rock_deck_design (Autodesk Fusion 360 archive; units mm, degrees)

design "rock_deck_design" references "PCB - Modulo", "rock_pcb", "rock_deck_lid_v2"
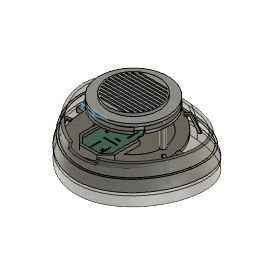
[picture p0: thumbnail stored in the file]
part number: 2025-12-11-21-33-59-411
part number: 2025-12-11-21-35-01-840
part number: 2025-12-11-22-10-40-260
part number: 2025-12-11-23-59-30-911
part number: 2025-12-12-00-11-13-812
part number: 2025-12-12-00-51-12-144
part number: 2025-12-12-02-11-26-460
part number: 2025-12-12-03-30-52-712
part number: 2025-12-12-20-44-37-742
part number: 2025-12-13-21-39-32-884
part number: 2025-12-13-21-39-32-904
part number: 2025-12-13-21-39-32-911
part number: 2025-12-14-05-35-21-238
parameter "led_outer" = 96
parameter "pcb_height" = 30
parameter "acrylic_height" = 3
parameter "d8" = 2.5
sketch "Sketch1" plane through (0, 0, 0) normal (0, 0, 1) x axis (1, 0, 0)
sketch "Sketch2" plane through (0, 0, 0) normal (0, 0, 1) x axis (1, 0, 0)
  circle C1 centre (0, 0) radius 48
  point P1 (0, 0)
  point P2 (0, 0)
  coincident P1 P2
  dimension "d3" diameter C1 = 96 (= "led_outer")
sketch "Sketch3" plane through (0, 0, 0) normal (0, 0, 1) x axis (1, 0, 0)
sketch "Sketch1" plane through (0, 0, 0) normal (0, 0, 1) x axis (1, 0, 0)
  line L1 (35.3875, -35.3231) -> (25.5948, -24.5999)
  line L2 (42.7648, -25.907) -> (31.0257, -17.2527)
  circle C1 centre (0, 0) radius 35.5
  arc A1 centre (0, 0) radius 50 clockwise from (35.3875, -35.3231) to (42.7648, -25.907)
  circle C2 centre (-12.1143, -8.7606) radius 1.25
  circle C3 centre (-16.5143, 28.7434) radius 1.25
  circle C4 centre (17.4857, 28.7434) radius 1.25
  circle C5 centre (11.8857, -8.7606) radius 1.25
  circle C6 centre (-12.1143, -8.7606) radius 1.25
  circle C7 centre (-16.5143, 28.7434) radius 1.25
  circle C8 centre (17.4857, 28.7434) radius 1.25
  circle C9 centre (11.8857, -8.7606) radius 1.25
  point P1 (0, 0)
  point P2 (0, 0)
  point P3 (0, 0)
  point P4 (25.5948, -24.5999)
  point P6 (31.0257, -17.2527)
  coincident P1 P2
  coincident P1 P3
  coincident C1 P4
  coincident C1 P6
  dimension "d9" diameter A1 = 100 (= "led_outer + 4 mm")
  dimension "d15" diameter C1 = 71 (= "led_outer - 25 mm")
  dimension "d216" diameter C5 = 2.5
  dimension "d217" diameter C2 = 2.5
  dimension "d218" diameter C4 = 2.5
  dimension "d219" diameter C3 = 2.5
  dimension "d220" diameter C9 = 2.5
  dimension "d221" diameter C6 = 2.5
  dimension "d222" diameter C8 = 2.5
  dimension "d223" diameter C7 = 2.5
extrude "Extrude1" new body sketch "Sketch1" profile of A1 against normal blind 2 bodies "lid_bottom"
sketch "Sketch2" plane through (0, 0, 0) normal (0, 0, 1) x axis (1, 0, 0)
extrude "Extrude2" add sketch "Sketch2" along normal blind 4.42
sketch "Sketch3" plane through (0, 0, 0) normal (0, 1, 0) x axis (1, 0, 0)
extrude "Extrude3" new body sketch "Sketch1" profile of C1 along normal blind 6
extrude "Extrude4" add sketch "Sketch1" profile of C1 against normal blind 4
extrude "Extrude5" add of existing geometry blind 2
extrude "Extrude6" add of existing geometry blind 1
sketch "Sketch4" plane through (0, 0, 7) normal (0, 0, 1) x axis (-1, 0, 0)
  circle C1 centre (0, 0) radius 35.5
  circle C2 centre (0, 0) radius 50
  point P1 (0, 0)
  point P3 (0, 0)
  coincident P1 P3
  dimension "d25" diameter C2 = 100 (= "led_outer + 4 mm")
extrude "Extrude7" new body sketch "Sketch4" along normal blind 3 (= "acrylic_height") bodies "Acrylic"
move "Move1"
component_insert "Component Insert2"
sketch "Sketch6" plane through (0, 0, 7) normal (0, 0, 1) x axis (-1, 0, 0)
  line L1 (-19, 44.4881) -> (20, 44.4881)
  line L2 (-19, -15.0119) -> (-19, 44.4881)
  line L3 (20, -15.0119) -> (-19, -15.0119)
  line L4 (20, 44.4881) -> (20, -15.0119)
  line L5 (9.5, 67.5) -> (-8.5, 67.5)
  line L6 (9.5, 49.5) -> (9.5, 67.5)
  line L7 (-8.5, 49.5) -> (9.5, 49.5)
  line L8 (-8.5, 67.5) -> (-8.5, 49.5)
  circle C1 centre (0, 0) radius 35.5
  circle C2 centre (11.8857, -8.7606) radius 1.25
  circle C3 centre (11.8857, -8.7606) radius 1.25
  circle C4 centre (-12.1143, -8.7606) radius 1.25
  circle C5 centre (17.4857, 28.7434) radius 1.25
  circle C6 centre (-16.5143, 28.7434) radius 1.25
  point P11 (11.8857, -8.7606)
  point P12 (11.8857, -8.7606)
  point P3 (20, 44.4881)
  point P4 (-19, 44.4881)
  point P6 (20, -15.0119)
  point P7 (-8.5, 67.5)
  point P8 (9.5, 67.5)
  point P10 (-8.5, 49.5)
  horizontal L1
  vertical L2
  horizontal L3
  vertical L4
  horizontal L5
  vertical L6
  horizontal L7
  vertical L8
  coincident P11 P12
  dimension "d32" distance P3 P4 = 39
  dimension "d33" distance P3 P6 = 59.5
  dimension "d34" distance P7 P8 = 18
  dimension "d35" distance P7 P10 = 18
  dimension "d46" diameter C2 = 2.5
  dimension "d48" diameter C3 = 2.5
  dimension "d213" diameter C4 = 2.5
  dimension "d214" diameter C5 = 2.5
  dimension "d215" diameter C6 = 2.5
extrude "Extrude8" new body sketch "Sketch6" profile of L1 L2 L3 L4 L5 L6 L7 L8 along normal blind 22
extrude "Extrude9" add of existing geometry blind 3
move "Move2"
move_face "MoveFace1"
move "Move3"
move "Move4"
move "Move5"
sketch "Sketch7" plane through (0, 0, -34.9) normal (0, 0, -1) x axis (1, 0, 0)
  line L1 (-140, -20.8619) -> (-140, 38.6381)
  line L2 (-101, -20.8619) -> (-140, -20.8619)
  line L3 (-101, 38.6381) -> (-101, -20.8619)
  line L4 (-140, 38.6381) -> (-101, 38.6381)
  line L5 (10.1267, 38.6381) -> (-9.8733, 38.6381)
  line L6 (10.1267, 36.0381) -> (10.1267, 38.6381)
  line L7 (-9.8733, 36.0381) -> (10.1267, 36.0381)
  line L8 (-9.8733, 38.6381) -> (-9.8733, 36.0381)
  point P6 (-9.8733, 38.6381)
  point P7 (10.1267, 38.6381)
  point P9 (-9.8733, 36.0381)
  horizontal L5
  vertical L6
  horizontal L7
  vertical L8
  coincident L4 P6
  dimension "d40" distance P6 P7 = 20
  dimension "d41" distance P6 P9 = 2.6
extrude "Extrude10" cut sketch "Sketch7" profile of L1 L2 L3 L4 L6 L7 L8 against normal blind 23
sketch "Sketch9" plane through (0, 0, -34.9) normal (0, 0, -1) x axis (1, 0, 0)
extrude "Extrude12" cut of existing geometry blind -60
component_from_bodies "Body->Comp2"
remove_instance "RemoveInstance1"
move_face "MoveFace2"
extrude "Extrude13" add of existing geometry blind 3
extrude "Extrude14" new body sketch "Sketch2" along normal blind 10
extrude "Extrude15" cut sketch "Sketch2" against normal blind 20
extrude "Extrude16" cut of existing geometry blind -5
extrude "Extrude17" cut of existing geometry blind -3.3
component_from_bodies "Body->Comp3"
copy_paste_bodies "CutPasteBodies1"
move "Move1"
extrude "Extrude1" cut of existing geometry blind -10 bodies "lid_bottom (1)"
extrude "Extrude5" cut of existing geometry blind -2
sketch "Sketch1" plane through (0, 0, -2) normal (0, 0, -1) x axis (1, 0, 0)
  line L1 (-29.3095, 19.0404) -> (-25.3095, 19.0404)
  line L2 (-29.3095, 49.4381) -> (-29.3095, 19.0404)
  line L3 (-25.3095, 19.0404) -> (-25.3095, 49.4381)
  line L4 (10, 59.5028) -> (-15.3954, 59.5028)
  line L5 (-15.3954, 63.5028) -> (10, 63.5028)
  line L6 (22.8952, 13.6845) -> (22.8952, 50.4973)
  line L7 (18.8952, 13.6845) -> (22.8952, 13.6845)
  line L8 (18.8952, 50.4973) -> (18.8952, 13.6845)
  line L9 (-15.3954, 63.5028) -> (-29.3095, 49.4381)
  line L10 (22.8952, 50.4973) -> (10, 63.5028)
  line L11 (18.8952, 50.4973) -> (10, 59.5028)
  line L12 (-25.3095, 49.4381) -> (-15.3954, 59.5028)
  line L13 (10.605, 22.1471) -> (2.605, 22.1471)
  line L14 (10.605, 18.1471) -> (10.605, 22.1471)
  line L15 (2.605, 18.1471) -> (10.605, 18.1471)
  line L16 (2.605, 22.1471) -> (2.605, 18.1471)
  curve K1 (-58.3992, -18.229) -> (-58.3992, -18.229)
  curve K2 (-32.0553, -67.1742) -> (3.8106, -67.1918)
  circle C1 centre (-14.2027, 1.6355) radius 0.75
  circle C2 centre (-14.2027, 1.6355) radius 2.5
  circle C3 centre (0, 0) radius 43
  point P24 (-14.1223, -67.183)
  point P3 (-25.3095, 19.0404)
  point P4 (-29.3095, 19.0404)
  point P7 (-15.3954, 59.5028)
  point P10 (-15.3954, 63.5028)
  point P11 (18.8952, 50.4973)
  point P12 (22.8952, 50.4973)
  point P16 (2.605, 22.1471)
  point P17 (10.605, 22.1471)
  point P19 (2.605, 18.1471)
  horizontal L1
  vertical L2
  vertical L3
  horizontal L4
  horizontal L5
  vertical L6
  horizontal L7
  vertical L8
  concentric C1 C2
  horizontal L13
  vertical L14
  horizontal L15
  vertical L16
  midpoint P24 K2
  dimension "d103" diameter C1 = 1.5
  dimension "d104" distance P3 P4 = 4
  dimension "d105" distance P7 P10 = 4
  dimension "d106" distance P11 P12 = 4
  dimension "d125" diameter C2 = 5
  dimension "d134" distance P16 P17 = 8
  dimension "d135" distance P16 P19 = 4
extrude "Extrude2" new body sketch "Sketch1" profile of L2 L3 L4 L5 L6 L8 L9 L10 L11 L12 against normal blind 6
extrude "Extrude3" add sketch "Sketch1" profile of L2 L3 L4 L5 L6 L8 L9 L10 L11 L12 along normal blind 2
extrude "Extrude4" add of existing geometry blind 2
move "Move1"
move "Move2"
extrude "Extrude5" new body sketch "Sketch1" profile of C1 along normal blind 6
extrude "Extrude6" add sketch "Sketch1" profile of C1 L1 L2 L3 L4 L6 L7 L8 L11 L12 along normal blind 4
extrude "Extrude7" cut of existing geometry blind -6
extrude "Extrude8" new body sketch "Sketch1" profile of C1 against normal blind 6
extrude "Extrude9" add of existing geometry blind 2
move_face "MoveFace1"
move "Move3"
extrude "Extrude10" add sketch "Sketch1" profile of C1 C2 against normal blind 4
extrude "Extrude11" cut of existing geometry blind -2
move "Move4"
extrude "Extrude12" new body sketch "Sketch1" profile of L1 L2 L3 L6 L7 L8 along normal blind 4
extrude "Extrude13" add sketch "Sketch1" profile of L1 L2 L3 L6 L7 L8 against normal blind 2
move "Move5"
position "Position1"
extrude "Extrude1" cut sketch "Sketch1" profile of L13 L14 L15 L16 along normal blind 50
move "Move6"
position "Position2"
extrude "Extrude15" add of existing geometry blind 4
extrude "Extrude16" add of existing geometry blind 2
cylinder_primitive "CylinderPrimitive1" Height 14 Diameter 15
move "Move7"
move "Move8"
move_face "MoveFace2"
move "Move9"
extrude "Extrude17" add of existing geometry blind 44
extrude "Extrude18" cut of existing geometry blind -5
extrude "Extrude19" cut of existing geometry blind -5
extrude "Extrude20" add of existing geometry blind 3
delete_face "DeleteFace1"
sketch "Sketch1" plane through (0, 0, 1.7) normal (0, 0, 1) x axis (-1, 0, 0)
  circle C1 centre (0, 0) radius 43
  circle C2 centre (-0.1571, 0.0176) radius 3.5
  circle C3 centre (0, -30) radius 2.5
  circle C4 centre (30, 0) radius 2.5
  circle C5 centre (0, 30) radius 2.5
  circle C6 centre (-30, 0) radius 2.5
  circle C7 centre (18.732, -19.3591) radius 2.5
  circle C8 centre (-19.9991, -19.3591) radius 2.5
  circle C9 centre (-20, 20) radius 2.5
  circle C10 centre (20, 20) radius 2.5
  dimension "d158" diameter C2 = 7
  dimension "d159" diameter C3 = 5
  dimension "d160" diameter C4 = 5
  dimension "d161" diameter C5 = 5
  dimension "d162" diameter C6 = 5
  dimension "d163" diameter C7 = 5
  dimension "d164" diameter C8 = 5
  dimension "d165" diameter C9 = 5
  dimension "d166" diameter C10 = 5
move_face "MoveFace3"
extrude "Extrude21" cut of existing geometry blind -10.4
move "Move8"
sketch "Sketch3" plane through (0, 0, 2.8) normal (0, 0, -1) x axis (1, 0, 0)
  circle C1 centre (0, 0) radius 40
  circle C2 centre (0, 0) radius 43
  dimension "d204" diameter C1 = 80
sketch "Sketch4" plane through (0, 0, -5.1) normal (0, 0, -1) x axis (1, 0, 0)
  circle C1 centre (0, 0) radius 43
sketch "Sketch1" plane through (0, 0, 1.7) normal (0, 0, 1) x axis (-1, 0, 0)
  circle C1 centre (0, 0) radius 35.5
  circle C2 centre (0, 0) radius 38
  point P1 (0, 0)
  point P3 (0, 0)
  coincident P1 P3
  dimension "d206" diameter C2 = 76 (= "led_outer - 20 mm")
extrude "Extrude1" new body sketch "Sketch1" against normal blind 11.6
sketch "Sketch2" plane through (0, 0, 1.7) normal (0, 0, 1) x axis (-1, 0, 0)
  circle C1 centre (0, 0) radius 43
  circle C2 centre (0, 0) radius 35.5
  point P1 (0, 0)
  point P3 (0, 0)
  coincident P1 P3
  dimension "d209" diameter C2 = 71 (= "led_outer - 25 mm")
extrude "Extrude2" add sketch "Sketch2" profile of C2 against normal blind 4
move "Move2"
extrude "Extrude1" new body sketch "Sketch6" profile of C2 C3 C4 C5 C6 along normal blind 5
move "Move1"
position "Position3"
extrude "Extrude18" cut of existing geometry blind -3
move "Move2"
component_insert "Component Insert2"
move "Move3"
move_face "MoveFace1"
move "Move4"
move "Move5"
move "Move6"
extrude "Extrude2" add of existing geometry blind 6
cylinder_primitive "CylinderPrimitive1" Height 5 Diameter 5
extrude "Extrude3" add of existing geometry blind 4
extrude "Extrude4" add of existing geometry blind 7
copy_paste_bodies "CopyPasteBodies1"
move "Move7"
copy_paste_bodies "CopyPasteBodies3"
move "Move9"
copy_paste_bodies "CopyPasteBodies4"
move "Move10"
delete_face "DeleteFace1"
delete_face "DeleteFace2"
position "Position5"
extrude "Extrude5" cut of existing geometry blind -10
extrude "Extrude3" add of existing geometry blind 7 bodies "lid_bottom (1)"
extrude "Extrude4" add of existing geometry blind 3.8
sketch "Sketch2" plane through (0, 0, -7.2307) normal (0, 0, -1) x axis (1, 0, 0)
  line L1 (35.4029, 35.2772) -> (30.6766, 30.1019)
  line L2 (37.1188, 21.6875) -> (42.7802, 25.8612)
  arc A1 centre (0.0154, -0.0459) radius 50 clockwise from (42.7802, 25.8612) to (35.4029, 35.2772)
  arc A2 centre (0.0154, -0.0459) radius 43 clockwise from (30.6766, 30.1019) to (37.1188, 21.6875)
  circle C1 centre (0, 0) radius 35.5
  point P1 (0, 0)
  point P7 (0, 0)
  coincident P1 P7
  dimension "d249" diameter C1 = 71 (= "led_outer - 20 mm - 5 mm")
extrude "Extrude6" cut sketch "Sketch2" profile of C1 against normal blind 10
extrude "Extrude7" add of existing geometry blind 10
extrude "Extrude8" cut of existing geometry blind -1
offset_faces "OffsetFaces1" distance -0.25
component_from_bodies "Body->Comp1"
component_insert "Component Insert3"
extrude "Extrude28" new body sketch "Sketch1" profile of C1 L1 L2 L3 L4 L5 L6 L7 L8 L9 L10 L11 L12 C2 L13 L14 L15 L16 C3 K1 along normal blind 4
move "Move11"
move_face "MoveFace5"
move "Move12"
position "Position6"
extrude "Extrude9" add of existing geometry blind 42
copy_paste_bodies "CutPasteBodies1"
extrude "Extrude29" cut of existing geometry blind -4
extrude "Extrude30" new body of existing geometry blind -15
move "Move13"
extrude "Extrude31" cut of existing geometry blind -11
copy_paste_bodies "CopyPasteBodies2"
move "Move6"
copy_paste_bodies "CopyPasteBodies3"
move "Move7"
move "Move8"
offset_faces "OffsetFaces1" distance 4
scale "Scale1" ScaleFactor 1.2
move "Move9"
extrude "Extrude8" cut of existing geometry blind -9
copy_paste_bodies "CopyPasteBodies4"
move "Move10"
sketch "Sketch6" plane through (0, 0, 0) normal (0, 1, 0) x axis (1, 0, 0)
  line L1 (-75.3685, 36.7721) -> (-58.2562, 36.7721)
  line L2 (-75.3685, 42.7721) -> (-75.3685, 36.7721)
  line L3 (-58.2562, 42.7721) -> (-75.3685, 42.7721)
  line L4 (-58.2562, 36.7721) -> (-58.2562, 42.7721)
  line L5 (-38.9696, 36.7721) -> (-58.2562, 42.7721)
  line L6 (-58.2562, 36.7721) -> (-38.9696, 36.7721)
  point P2 (-58.2562, 36.7721)
  point P5 (-58.2562, 42.7721)
  horizontal L1
  vertical L2
  horizontal L3
  vertical L4
  perpendicular L4 L6
  dimension "d285" distance P2 P5 = 6
extrude "Extrude34" new body sketch "Sketch6" along normal blind 8 and against normal blind 8
hole "Hole1" HoleDepth 6 HoleDiameter 9 TipAngle 180
copy_paste_bodies "CopyPasteBodies3"
move "Move17"
scale "Scale2" ScaleFactor 1.1
move "Move11"
move "Move12"
offset_faces "OffsetFaces2" distance 10
extrude "Extrude9" cut of existing geometry blind -11
copy_paste_bodies "CopyPasteBodies5"
copy_paste_bodies "CopyPasteBodies6"
copy_paste_bodies "CopyPasteBodies7"
move "Move13"
component_from_bodies "Body->Comp2"
component_from_bodies "Body->Comp3"
component_from_bodies "Body->Comp4"
offset_faces "OffsetFaces3" distance 1
fillet "Fillet1" radius 0.25
sketch "Sketch4" plane through (0, 0, 0) normal (1, 0, 0) x axis (0, 1, 0)
  line L1 (-8.1721, -54.9092) -> (7.2337, -54.9092)
  line L2 (-12.1755, -57.6931) -> (-8.1721, -54.9092)
  line L3 (11.5268, -57.6931) -> (-12.1755, -57.6931)
  line L4 (7.2337, -54.9092) -> (11.5268, -57.6931)
  line L5 (7.2337, -54.9092) -> (12, -58)
  point P6 (7.2337, -54.9092)
  horizontal L1
  parallel L1 L3
  coincident L4 P6
  coincident L1 P6
  parallel L4 L5
copy_paste_bodies "CopyPasteBodies8"
copy_paste_bodies "CopyPasteBodies9"
move "Move14"
move "Move15"
move "Move16"
move "Move17"
offset_faces "OffsetFaces4" distance -1.28
sketch "Sketch3" plane through (0, 0, -57.536) normal (0, 0, -1) x axis (1, 0, 0)
  curve K1 (20.2695, -72.7724) -> (20.2695, -72.7724)
  line L1 (-15, 11.5) -> (15, 11.5)
  line L2 (-15, 8.5) -> (-15, 11.5)
  line L3 (15, 8.5) -> (-15, 8.5)
  line L4 (15, 11.5) -> (15, 8.5)
  line L5 (-15, 8.5) -> (15, 11.5)
  line L6 (15, 8.5) -> (-15, 11.5)
  curve K2 (20.2695, -72.7724) -> (20.2695, -72.7724)
  circle C1 centre (0, 10) radius 7.25
  circle C2 centre (0, 10) radius 4.75
  circle C3 centre (0, 10) radius 7.25
  point P10 (0, 10)
  point P5 (0, 10)
  point P8 (-15, 8.5)
  point P9 (15, 8.5)
  point P7 (-15, 11.5)
  concentric C1 C2
  horizontal L1
  perpendicular L1 L2
  parallel L1 L3
  parallel L2 L4
  coincident L5 P10
  coincident L6 P10
  coincident P5 P10
  dimension "d322" diameter C2 = 9.5
  dimension "d323" distance P8 P9 = 30
  dimension "d324" distance P7 P8 = 3
sketch "Sketch4" plane through (0, 0, 0) normal (0, 0, 1) x axis (1, 0, 0)
  line L1 (-15, -8.5) -> (-15, -11.5)
  line L2 (15, -8.5) -> (-15, -8.5)
  line L3 (15, -11.5) -> (15, -8.5)
  line L4 (-15, -8.5) -> (15, -11.5)
  line L5 (15, -8.5) -> (-15, -11.5)
  circle C1 centre (0, -10) radius 5
  point P7 (0, -10)
  point P2 (0, -10)
  point P5 (-15, -8.5)
  point P6 (15, -8.5)
  point P4 (-15, -11.5)
  parallel L1 L3
  coincident L4 P7
  coincident L5 P7
  coincident P2 P7
  dimension "d325" diameter C1 = 10
  dimension "d326" distance P5 P6 = 30
  dimension "d327" distance P4 P5 = 3
extrude "Extrude10" add of existing geometry blind 14
sketch "Sketch5" plane through (0, 0, 0) normal (0, 1, 0) x axis (1, 0, 0)
  line L1 (6.6201, 61.3271) -> (-6.6961, 61.3271)
  line L2 (-6.6961, 75.4116) -> (6.6201, 75.4116)
  line L3 (-13.6103, 73.3629) -> (-6.6961, 73.3629)
  line L4 (-13.6103, 68.3693) -> (-13.6103, 73.3629)
  line L5 (-6.6961, 68.3693) -> (-10.6103, 68.3693)
  line L6 (-10.6103, 56.9972) -> (-10.6103, 68.3693)
  line L7 (-13.6103, 56.9972) -> (-10.6103, 56.9972)
  line L8 (-13.6103, 68.3693) -> (-13.6103, 56.9972)
  line L9 (11.3025, 68.3693) -> (6.6201, 68.3693)
  line L10 (14.3025, 73.491) -> (14.3025, 68.3693)
  line L11 (6.6201, 73.491) -> (14.3025, 73.491)
  line L12 (11.3025, 57.4859) -> (11.3025, 68.3693)
  line L13 (14.3025, 57.4859) -> (11.3025, 57.4859)
  line L14 (14.3025, 68.3693) -> (14.3025, 57.4859)
  line L15 (-6.6961, 73.3629) -> (-6.6961, 75.4116)
  line L16 (-6.6961, 61.3271) -> (-6.6961, 68.3693)
  line L17 (6.6201, 68.3693) -> (6.6201, 61.3271)
  line L18 (6.6201, 75.4116) -> (6.6201, 73.491)
  point P8 (-13.6103, 68.3693)
  point P10 (-10.6103, 68.3693)
  point P14 (14.3025, 68.3693)
  point P17 (11.3025, 68.3693)
  horizontal L1
  vertical L17
  horizontal L2
  vertical L15
  horizontal L3
  vertical L4
  horizontal L5
  vertical L6
  horizontal L7
  vertical L8
  horizontal L9
  vertical L10
  horizontal L11
  vertical L12
  horizontal L13
  vertical L14
  collinear L15 L16
  collinear L17 L18
  dimension "d344" distance P8 P10 = 3
  dimension "d345" distance P14 P17 = 3
extrude "Extrude11" cut sketch "Sketch5" profile of L1 L18 L2 L16 L3 L4 L5 L6 L7 L8 L9 L10 L11 L12 L13 L14 distance 4.8
sketch "Sketch6" plane through (0, 0, 0) normal (0, 1, 0) x axis (1, 0, 0)
position "Position7"
extrude "Extrude12" cut blind 24 second side blind 0
extrude "Extrude14" new body blind 26.5 second side blind 6
extrude "Extrude15" add blind 24
extrude "Extrude16" new body blind 24
extrude "Extrude17" add blind 25.5 second side blind -24
extrude "Extrude18" add blind 26 second side blind -24
extrude "Extrude19" add blind -0.5
extrude "Extrude20" add of existing geometry blind 0.5
extrude "Extrude22" add of existing geometry blind 15
extrude "Extrude23" cut of existing geometry blind -29
extrude "Extrude25" new body distance 2
path_pattern "PathPattern2" PathPatternDelta 85
move "Move21"
loft "Loft1" sketch "Sketch3"
sketch "Sketch7" plane through (0, 0, 0) normal (0, 1, 0) x axis (1, 0, 0)
form "Form1"
position "Position8"
sketch "Sketch8" plane through (0, 0, 0) normal (0, 1, 0) x axis (1, 0, 0)
  line L1 (-20, 27) -> (20, 27)
  line L2 (-20, 33) -> (-20, 27)
  line L3 (20, 33) -> (-20, 33)
  line L4 (20, 27) -> (20, 33)
  line L5 (-20, 33) -> (20, 27)
  line L6 (20, 33) -> (-20, 27)
  point P6 (0, 30)
  point P4 (-20, 33)
  point P5 (20, 33)
  point P3 (-20, 27)
  horizontal L1
  perpendicular L1 L2
  parallel L1 L3
  parallel L2 L4
  coincident L5 P6
  coincident L6 P6
  dimension "d496" distance P4 P5 = 40
  dimension "d497" distance P3 P4 = 6
extrude "Extrude26" cut sketch "Sketch8" profile of L1 L2 L3 L4 against normal blind 25
extrude "Extrude27" cut of existing geometry blind -4
delete_face "DeleteFace1"
box_primitive "BoxPrimitive1" DistanceX 5 DistanceY 15 DistanceZ -20 OffsetDistanceX 0 OffsetDistanceY 0
sketch "Sketch10" plane through (0, 0, 0) normal (1, 0, 0) x axis (0, 1, 0)
  line L1 (-102.9054, -42.8602) -> (100.4555, -42.8602)
  horizontal L1
extrude "Extrude13" new body blind 120 second side blind 130
delete_face "DeleteFace2"
split "Split1"
sketch "Sketch11" plane through (0, 0, -42.8602) normal (0, 0, -1) x axis (1, 0, 0)
  curve K1 (20.9582, -66.5357) -> (20.9582, -66.5357)
  curve K2 (21.2287, -69.2751) -> (21.2287, -69.2751)
  dimension "d516" = -2
extrude "Extrude14" new body sketch "Sketch11" profile of K1 along normal blind 2
surface_delete_face "SurfaceDeleteFace1"
extrude "Extrude15" add of existing geometry blind 1
extrude "Extrude28" add of existing geometry blind 0.2
extrude "Extrude16" add of existing geometry blind 5
delete_face "DeleteFace3"
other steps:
base_feature "Base Feature1"
base_feature "Base Feature1"
base_feature "Base Feature1"
base_feature "Base Feature1"
base_feature "Base Feature1"
base_feature "Base Feature1" bodies "lid_bottom"
base_feature "Base Feature2"
move "Move1"
extrude "Extrude3" cut of existing geometry blind -10
extrude "Extrude4" cut sketch "Sketch2" profile of C1 against normal blind 10
extrude "Extrude2" cut of existing geometry blind -3
move "Move1"
extrude "Extrude5" cut sketch "Sketch2" profile of C1 against normal blind 10
base_feature "Base Feature1"
base_feature "Base Feature3"
base_feature "Base Feature4"
move "Move9"
base_feature "Base Feature2"
base_feature "Base Feature3"
base_feature "Base Feature4"
hole "Hole1" HoleDepth 6 HoleDiameter 9 TipAngle 180
base_feature "Base Feature5"
base_feature "Base Feature6"
base_feature "Base Feature7"
base_feature "Base Feature8"
base_feature "Base Feature9"
extrude "Extrude14" cut sketch "Sketch1" profile of L13 L14 L15 L16 along normal blind 50
base_feature "Base Feature1"
move "Move14"
base_feature "Base Feature3"
create_component "CreateComponent1"
create_component "CreateComponent1"
create_component "CreateComponent2"
reparent_decal "ReparentDecal2"
remove_body "RemoveBody2"
create_component "CreateComponent3"
reparent_decal "ReparentDecal4"
remove_body "RemoveBody4"
reparent_decal "ReparentDecal5"
remove_body "RemoveBody5"
create_component "CreateComponent3"
create_component "CreateComponent4"
create_component "CreateComponent1"
create_component "CreateComponent2"
reparent_decal "ReparentDecal1"
remove_body "RemoveBody1"
reparent_decal "ReparentDecal2"
remove_body "RemoveBody2"
reparent_decal "ReparentDecal3"
remove_body "RemoveBody3"
reparent_decal "ReparentDecal4"
remove_body "RemoveBody4"
create_component "CreateComponent3"
reparent_decal "ReparentDecal5"
remove_body "RemoveBody5"
create_component "CreateComponent4"
reparent_decal "ReparentDecal6"
remove_body "RemoveBody6"
create_component "CreateComponent5"
reparent_decal "ReparentDecal7"
remove_body "RemoveBody7"
create_component "CreateComponent7"
named bodies: "lid_bottom", "Acrylic", "lid_bottom (1)"

design "PCB - Modulo"
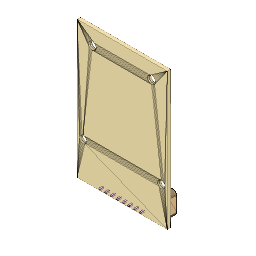
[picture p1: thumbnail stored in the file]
base_mesh_feature "Base Mesh Feature"

design "rock_pcb"
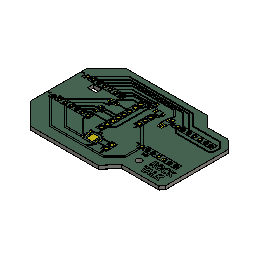
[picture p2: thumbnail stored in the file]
description: KiCad electronic assembly
part number: rock_pcb 1
description: Part Number
part number: rock_pcb_copper
part number: rock_pcb_pad
part number: rock_pcb_silkscreen
part number: rock_pcb_soldermask
part number: rock_pcb_PCB
base_feature "Base Feature1"
base_feature "Base Feature1"
base_feature "Base Feature1"
base_feature "Base Feature1"
base_feature "Base Feature1"
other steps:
create_component "CreateComponent1"
create_component "CreateComponent2"
create_component "CreateComponent3"
create_component "CreateComponent4"
create_component "CreateComponent5"

design "rock_deck_lid_v2"
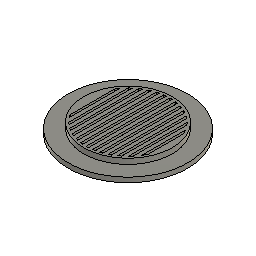
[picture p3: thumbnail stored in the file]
description: Part Number
part number: 2025-12-12-21-32-44-879
base_feature "Base Feature"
